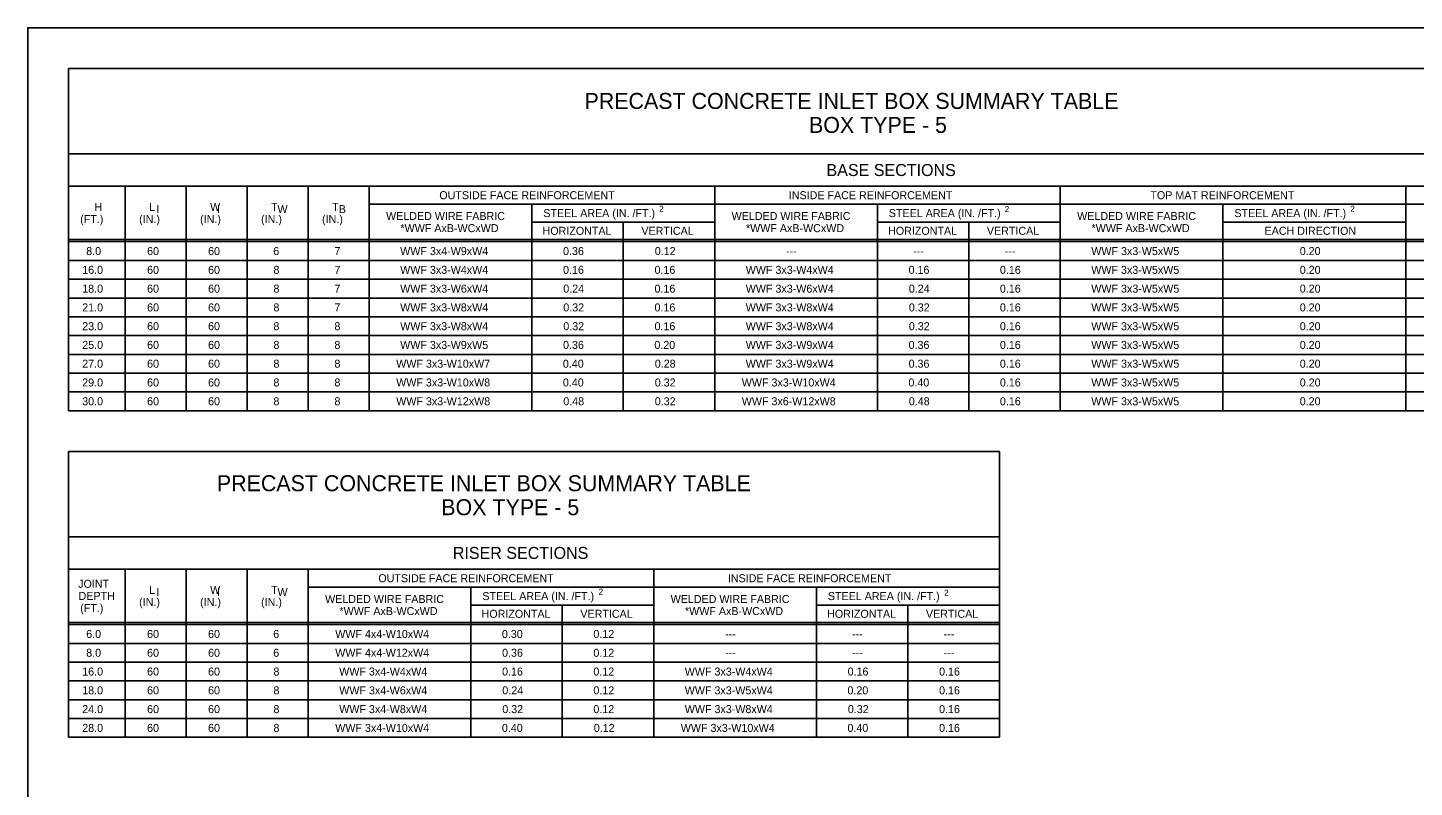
# Model space of a CAD drawing. Extents: x -6420 to 49575, y -4552 to 11624.
# Drawn here: x -3533 to -1828, y -1052 to -118 of the extents above; entities that cross this region are included whole.
import ezdxf

# ---------------------------------------------------------------- set-up
doc = ezdxf.new("R2010")
doc.units = 0
doc.layers.add('1', color=7, linetype='Continuous')

msp = doc.modelspace()

# ---------------------------------------------------------------- linework, layer by layer
at = {"layer": '1'}
for p, q in [((-3483.2, -168.2), (-3483.2, -589.2)), ((-1413.2, -168.2), (-3483.2, -168.2)), ((-1413.2, -273.2), (-3483.2, -273.2)), ((-1413.2, -313.2), (-3483.2, -313.2)), ((-3413.2, -589.2), (-3413.2, -313.2)), ((-3338.2, -313.2), (-3338.2, -589.2)), ((-3263.2, -313.2), (-3263.2, -589.2)), ((-3188.2, -313.2), (-3188.2, -589.2)), ((-3113.2, -313.2), (-3113.2, -589.2)), ((-2688.2, -313.2), (-2688.2, -589.2)), ((-2263.2, -313.2), (-2263.2, -589.2)), ((-1838.2, -313.2), (-1838.2, -589.2)), ((-3113.2, -335.2), (-2688.2, -335.2)), ((-2913.2, -335.2), (-2913.2, -589.2)), ((-2688.2, -335.2), (-1413.2, -335.2)), ((-2488.2, -335.2), (-2488.2, -589.2)), ((-2063.2, -335.2), (-2063.2, -589.2)), ((-2913.2, -357.2), (-2688.2, -357.2)), ((-2800.7, -357.2), (-2800.7, -589.2)), ((-2488.2, -357.2), (-2263.2, -357.2)), ((-2375.7, -357.2), (-2375.7, -589.2)), ((-2063.2, -357.2), (-1838.2, -357.2)), ((-3483.2, -378.8), (-1413.2, -378.8)), ((-3483.2, -381.3), (-1413.2, -381.3)), ((-3483.2, -404.4), (-1413.2, -404.4)), ((-3483.2, -427.5), (-1413.2, -427.5)), ((-3483.2, -450.6), (-1413.2, -450.6)), ((-3483.2, -473.7), (-1413.2, -473.7)), ((-3483.2, -496.8), (-1413.2, -496.8)), ((-3483.2, -519.9), (-1413.2, -519.9)), ((-3483.2, -543), (-1413.2, -543)), ((-3483.2, -566.1), (-1413.2, -566.1)), ((-3483.2, -589.2), (-1413.2, -589.2)), ((-3483.2, -639.2), (-3483.2, -990.8)), ((-2338.2, -639.2), (-3483.2, -639.2)), ((-2338.2, -639.2), (-2338.2, -990.8)), ((-2338.2, -744.2), (-3483.2, -744.2)), ((-2338.2, -784.2), (-3483.2, -784.2)), ((-3413.2, -990.8), (-3413.2, -784.2)), ((-3338.2, -784.2), (-3338.2, -990.8)), ((-3263.2, -784.2), (-3263.2, -990.8)), ((-3188.2, -784.2), (-3188.2, -990.8)), ((-2763.2, -784.2), (-2763.2, -990.8)), ((-3188.2, -806.2), (-2763.2, -806.2)), ((-2988.2, -806.2), (-2988.2, -990.8)), ((-2763.2, -806.2), (-2338.2, -806.2)), ((-2563.2, -806.2), (-2563.2, -990.8)), ((-2988.2, -828.2), (-2763.2, -828.2)), ((-2875.7, -828.2), (-2875.7, -990.8)), ((-2563.2, -828.2), (-2338.2, -828.2)), ((-2450.7, -828.2), (-2450.7, -990.8)), ((-3483.2, -849.8), (-2338.2, -849.8)), ((-3483.2, -852.2), (-2338.2, -852.2)), ((-3483.2, -875.3), (-2338.2, -875.3)), ((-3483.2, -898.4), (-2338.2, -898.4)), ((-3483.2, -921.5), (-2338.2, -921.5)), ((-3483.2, -944.6), (-2338.2, -944.6)), ((-3483.2, -967.7), (-2338.2, -967.7)), ((-3483.2, -990.8), (-2338.2, -990.8))]:
    msp.add_line(p, q, dxfattribs=at)
msp.add_lwpolyline([(-954.5, -1968.6), (-954.5, -118.2), (-3533.2, -118.2), (-3533.2, -1968.6), (-954.5, -1968.6), (-954.5, -1882.1), (-1610.7, -1882.1), (-1610.7, -1669.9), (-954.5, -1669.9), (-954.5, -1574.9), (-1610.7, -1574.9), (-1610.7, -1968.6), (-1352.1, -1968.6), (-1352.1, -1882.1), (-1352.1, -1968.6), (-1099.5, -1968.6), (-1099.5, -1882.1), (-1099.5, -1922.6), (-954.5, -1922.6)], dxfattribs=at)

# ---------------------------------------------------------------- texts
for s, height, p in [('PRECAST CONCRETE INLET BOX SUMMARY TABLE', 19.685, (-2848.4, -218.1)), ('BOX TYPE - 5', 19.685, (-2572.3, -247.6)), ('BASE SECTIONS', 14.764, (-2550.8, -300.6)), ('OUTSIDE FACE REINFORCEMENT', 9.843, (-3027, -329.1)), ('INSIDE FACE REINFORCEMENT', 9.843, (-2597.1, -329.1)), ('TOP MAT REINFORCEMENT', 9.843, (-2152.4, -329.1)), ('H', 9.84, (-3451, -343.5)), ('L ', 9.84, (-3383.9, -343.5)), ('I', 9.84, (-3374.9, -346.1)), ('W ', 9.84, (-3308.9, -343.5)), ('I', 9.84, (-3300.5, -346)), ('T ', 9.84, (-3233.9, -343.5)), ('W', 9.84, (-3226, -346.2)), ('T ', 9.84, (-3158.9, -343.5)), ('B', 9.84, (-3150.7, -346.2)), ('STEEL AREA (IN. /FT.)', 9.843, (-2899.1, -351.1)), ('2', 7.5, (-2756.6, -344.5)), ('STEEL AREA (IN. /FT.)', 9.843, (-2474.1, -351.1)), ('2', 7.5, (-2331.6, -345)), ('STEEL AREA (IN. /FT.)', 9.843, (-2049.1, -351.1)), ('2', 7.5, (-1906.5, -344.5)), ('(FT.)', 9.84, (-3468.7, -358.4)), ('(IN.)', 9.84, (-3396.2, -358.4)), ('(IN.)', 9.84, (-3321.2, -358.4)), ('(IN.)', 9.84, (-3246.2, -358.4)), ('(IN.)', 9.84, (-3171.2, -358.4)), ('WELDED WIRE FABRIC', 9.843, (-3092.5, -354.7)), ('WELDED WIRE FABRIC', 9.843, (-2667.5, -354.7)), ('WELDED WIRE FABRIC', 9.843, (-2242.5, -354.7)), ('*WWF AxB-WCxWD', 9.843, (-3074.8, -369.6)), ('HORIZONTAL', 9.84, (-2900, -372.9)), ('VERTICAL', 9.84, (-2778.5, -372.9)), ('*WWF AxB-WCxWD', 9.843, (-2649.8, -369.6)), ('HORIZONTAL', 9.84, (-2475, -372.9)), ('VERTICAL', 9.84, (-2353.5, -372.9)), ('*WWF AxB-WCxWD', 9.843, (-2224.8, -369.6)), ('EACH DIRECTION', 9.843, (-2012, -372.9)), ('8.0', 9.84, (-3461.3, -397.8)), ('60', 9.84, (-3386.4, -397.8)), ('60', 9.84, (-3311.4, -397.8)), ('6', 9.84, (-3231.3, -397.8)), ('7', 9.84, (-3156, -397.8)), ('WWF 3x4-W9xW4', 9.843, (-3075.1, -397.8)), ('0.36', 9.84, (-2874.8, -397.8)), ('0.12', 9.84, (-2762, -397.8)), ('WWF 3x3-W5xW5', 9.843, (-2225.1, -397.8)), ('0.20', 9.84, (-1968.7, -397.8)), ('---', 9.84, (-2600.5, -397.8)), ('---', 9.84, (-2444.2, -397.8)), ('---', 9.84, (-2331.7, -397.8)), ('16.0', 9.84, (-3466.2, -420.9)), ('60', 9.84, (-3386.4, -420.9)), ('60', 9.84, (-3311.4, -420.9)), ('8', 9.84, (-3231, -420.9)), ('7', 9.84, (-3156, -420.9)), ('WWF 3x3-W4xW4', 9.843, (-3075.1, -420.9)), ('0.16', 9.84, (-2874.8, -420.9)), ('0.16', 9.84, (-2762.3, -420.9)), ('WWF 3x3-W4xW4', 9.843, (-2650.1, -420.9)), ('0.16', 9.84, (-2449.8, -420.9)), ('0.16', 9.84, (-2337.5, -420.9)), ('WWF 3x3-W5xW5', 9.843, (-2225.1, -420.9)), ('0.20', 9.84, (-1968.7, -420.9)), ('18.0', 9.84, (-3466.2, -444)), ('60', 9.84, (-3386.4, -444)), ('60', 9.84, (-3311.4, -444)), ('8', 9.84, (-3231, -444)), ('7', 9.84, (-3156, -444)), ('WWF 3x3-W6xW4', 9.843, (-3075.1, -444)), ('0.24', 9.84, (-2874.5, -444)), ('0.16', 9.84, (-2762.3, -444)), ('WWF 3x3-W6xW4', 9.843, (-2650.1, -444)), ('0.24', 9.84, (-2449.5, -444)), ('0.16', 9.84, (-2337.5, -444)), ('WWF 3x3-W5xW5', 9.843, (-2225.1, -444)), ('0.20', 9.84, (-1968.7, -444)), ('21.0', 9.84, (-3466.2, -467.1)), ('60', 9.84, (-3386.4, -467.1)), ('60', 9.84, (-3311.4, -467.1)), ('8', 9.84, (-3231, -467.1)), ('7', 9.84, (-3156, -467.1)), ('WWF 3x3-W8xW4', 9.843, (-3075.1, -467.1)), ('0.32', 9.84, (-2874.5, -467.1)), ('0.16', 9.84, (-2762.3, -467.1)), ('WWF 3x3-W8xW4', 9.843, (-2650.1, -467.1)), ('0.32', 9.84, (-2449.5, -467.1)), ('0.16', 9.84, (-2337.5, -467.1)), ('WWF 3x3-W5xW5', 9.843, (-2225.1, -467.1)), ('0.20', 9.84, (-1968.7, -467.1)), ('23.0', 9.84, (-3466.2, -490.2)), ('60', 9.84, (-3386.4, -490.2)), ('60', 9.84, (-3311.4, -490.2)), ('8', 9.84, (-3231, -490.2)), ('8', 9.84, (-3156, -490.2)), ('WWF 3x3-W8xW4', 9.843, (-3075.1, -490.2)), ('0.32', 9.84, (-2874.5, -490.2)), ('0.16', 9.84, (-2762.3, -490.2)), ('WWF 3x3-W8xW4', 9.843, (-2650.1, -490.2)), ('0.32', 9.84, (-2449.5, -490.2)), ('0.16', 9.84, (-2337.5, -490.2)), ('WWF 3x3-W5xW5', 9.843, (-2225.1, -490.2)), ('0.20', 9.84, (-1968.7, -490.2)), ('25.0', 9.84, (-3466.2, -513.2)), ('60', 9.84, (-3386.4, -513.2)), ('60', 9.84, (-3311.4, -513.2)), ('8', 9.84, (-3231, -513.2)), ('8', 9.84, (-3156, -513.2)), ('WWF 3x3-W9xW5', 9.843, (-3075.1, -513.2)), ('0.36', 9.84, (-2874.8, -513.2)), ('0.20', 9.84, (-2762.5, -513.2)), ('WWF 3x3-W9xW4', 9.843, (-2650.1, -513.2)), ('0.36', 9.84, (-2449.8, -513.2)), ('0.16', 9.84, (-2337.5, -513.2)), ('WWF 3x3-W5xW5', 9.843, (-2225.1, -513.2)), ('0.20', 9.84, (-1968.7, -513.2)), ('27.0', 9.84, (-3466.2, -536.3)), ('60', 9.84, (-3386.4, -536.3)), ('60', 9.84, (-3311.4, -536.3)), ('8', 9.84, (-3231, -536.3)), ('8', 9.84, (-3156, -536.3)), ('WWF 3x3-W10xW7', 9.843, (-3080, -536.3)), ('0.40', 9.84, (-2875, -536.3)), ('0.28', 9.84, (-2762, -536.3)), ('WWF 3x3-W9xW4', 9.843, (-2650.1, -536.3)), ('0.36', 9.84, (-2449.8, -536.3)), ('0.16', 9.84, (-2337.5, -536.3)), ('WWF 3x3-W5xW5', 9.843, (-2225.1, -536.3)), ('0.20', 9.84, (-1968.7, -536.3)), ('29.0', 9.84, (-3466.2, -559.4)), ('60', 9.84, (-3386.4, -559.4)), ('60', 9.84, (-3311.4, -559.4)), ('8', 9.84, (-3231, -559.4)), ('8', 9.84, (-3156, -559.4)), ('WWF 3x3-W10xW8', 9.843, (-3080, -559.4)), ('0.40', 9.84, (-2875, -559.4)), ('0.32', 9.84, (-2762, -559.4)), ('WWF 3x3-W10xW4', 9.843, (-2655, -559.4)), ('0.40', 9.84, (-2450, -559.4)), ('0.16', 9.84, (-2337.5, -559.4)), ('WWF 3x3-W5xW5', 9.843, (-2225.1, -559.4)), ('0.20', 9.84, (-1968.7, -559.4)), ('30.0', 9.84, (-3466.2, -582.5)), ('60', 9.84, (-3386.4, -582.5)), ('60', 9.84, (-3311.4, -582.5)), ('8', 9.84, (-3231, -582.5)), ('8', 9.84, (-3156, -582.5)), ('WWF 3x3-W12xW8', 9.843, (-3080, -582.5)), ('0.48', 9.84, (-2874.5, -582.5)), ('0.32', 9.84, (-2762, -582.5)), ('WWF 3x6-W12xW8', 9.843, (-2655, -582.5)), ('0.48', 9.84, (-2449.5, -582.5)), ('0.16', 9.84, (-2337.5, -582.5)), ('WWF 3x3-W5xW5', 9.843, (-2225.1, -582.5)), ('0.20', 9.84, (-1968.7, -582.5)), ('PRECAST CONCRETE INLET BOX SUMMARY TABLE', 19.685, (-3300.6, -688.2)), ('BOX TYPE - 5', 19.685, (-3024.6, -717.7)), ('RISER SECTIONS', 14.764, (-3010.4, -771.5)), ('JOINT', 9.84, (-3471.2, -807)), ('OUTSIDE FACE REINFORCEMENT', 9.843, (-3102, -800.1)), ('INSIDE FACE REINFORCEMENT', 9.843, (-2672.1, -800.1)), ('DEPTH', 9.84, (-3470.7, -821.9)), ('L ', 9.84, (-3383.9, -814.5)), ('I', 9.84, (-3374.9, -817)), ('W ', 9.84, (-3308.9, -814.5)), ('I', 9.84, (-3300.5, -817)), ('T ', 9.84, (-3233.9, -814.5)), ('W', 9.84, (-3226, -817.2)), ('WELDED WIRE FABRIC', 9.843, (-3167.5, -825.7)), ('STEEL AREA (IN. /FT.)', 9.843, (-2974.1, -822.1)), ('2', 7.5, (-2831.1, -815.7)), ('WELDED WIRE FABRIC', 9.843, (-2742.5, -825.7)), ('STEEL AREA (IN. /FT.)', 9.843, (-2549.1, -822.1)), ('2', 7.5, (-2406.1, -816.7)), ('(FT.)', 9.84, (-3468.7, -836.7)), ('(IN.)', 9.84, (-3396.2, -829.3)), ('(IN.)', 9.84, (-3321.2, -829.3)), ('(IN.)', 9.84, (-3246.2, -829.3)), ('*WWF AxB-WCxWD', 9.843, (-3149.8, -840.5)), ('HORIZONTAL', 9.84, (-2975, -843.9)), ('VERTICAL', 9.84, (-2853.5, -843.9)), ('*WWF AxB-WCxWD', 9.843, (-2724.8, -840.5)), ('HORIZONTAL', 9.84, (-2550, -843.9)), ('VERTICAL', 9.84, (-2428.5, -843.9)), ('6.0', 9.84, (-3461.3, -868.7)), ('60', 9.84, (-3386.4, -868.7)), ('60', 9.84, (-3311.4, -868.7)), ('6', 9.84, (-3231.3, -868.7)), ('WWF 4x4-W10xW4', 9.843, (-3155, -868.7)), ('0.30', 9.84, (-2950, -868.7)), ('0.12', 9.84, (-2837.5, -868.7)), ('---', 9.84, (-2675.5, -868.7)), ('---', 9.84, (-2519.2, -868.7)), ('---', 9.84, (-2406.7, -868.7)), ('8.0', 9.84, (-3461.3, -891.8)), ('60', 9.84, (-3386.4, -891.8)), ('60', 9.84, (-3311.4, -891.8)), ('6', 9.84, (-3231.3, -891.8)), ('WWF 4x4-W12xW4', 9.843, (-3155, -891.8)), ('0.36', 9.84, (-2949.8, -891.8)), ('0.12', 9.84, (-2837.5, -891.8)), ('---', 9.84, (-2675.5, -891.8)), ('---', 9.84, (-2519.2, -891.8)), ('---', 9.84, (-2406.7, -891.8)), ('16.0', 9.84, (-3466.2, -914.9)), ('60', 9.84, (-3386.4, -914.9)), ('60', 9.84, (-3311.4, -914.9)), ('8', 9.84, (-3231, -914.9)), ('WWF 3x4-W4xW4', 9.843, (-3150.1, -914.9)), ('0.16', 9.84, (-2949.8, -914.9)), ('0.12', 9.84, (-2837.5, -914.9)), ('WWF 3x3-W4xW4', 9.843, (-2725.1, -914.9)), ('0.16', 9.84, (-2524.8, -914.9)), ('0.16', 9.84, (-2412.3, -914.9)), ('18.0', 9.84, (-3466.2, -938)), ('60', 9.84, (-3386.4, -938)), ('60', 9.84, (-3311.4, -938)), ('8', 9.84, (-3231, -938)), ('WWF 3x4-W6xW4', 9.843, (-3150.1, -938)), ('0.24', 9.84, (-2949.5, -938)), ('0.12', 9.84, (-2837.5, -938)), ('WWF 3x3-W5xW4', 9.843, (-2725.1, -938)), ('0.20', 9.84, (-2525, -938)), ('0.16', 9.84, (-2412.3, -938)), ('24.0', 9.84, (-3466.2, -961.1)), ('60', 9.84, (-3386.4, -961.1)), ('60', 9.84, (-3311.4, -961.1)), ('8', 9.84, (-3231, -961.1)), ('WWF 3x4-W8xW4', 9.843, (-3150.1, -961.1)), ('0.32', 9.84, (-2949.5, -961.1)), ('0.12', 9.84, (-2837.5, -961.1)), ('WWF 3x3-W8xW4', 9.843, (-2725.1, -961.1)), ('0.32', 9.84, (-2524.5, -961.1)), ('0.16', 9.84, (-2412.3, -961.1)), ('28.0', 9.84, (-3466.2, -984.2)), ('60', 9.84, (-3386.4, -984.2)), ('60', 9.84, (-3311.4, -984.2)), ('8', 9.84, (-3231, -984.2)), ('WWF 3x4-W10xW4', 9.843, (-3155, -984.2)), ('0.40', 9.84, (-2950, -984.2)), ('0.12', 9.84, (-2837, -984.2)), ('WWF 3x3-W10xW4', 9.843, (-2730, -984.2)), ('0.40', 9.84, (-2525, -984.2)), ('0.16', 9.84, (-2412.3, -984.2))]:
    msp.add_text(s, height=height, dxfattribs=at).set_placement(p)

doc.saveas('drawing.dxf')
